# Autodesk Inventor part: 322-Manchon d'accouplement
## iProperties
Author: Philippe
Created: 2001-12
Part Number: 322-Manchon d'accouplement
Material: Par défaut
Document SubType Name: Modélisation
Designer: Philippe
Control State: 0
Master: False
Checked Out: False
PropertySet Name: Design Tracking Control
Shininess: 50.0
Angle Display Precision: 2
Document Length Units: 11269
Document Angle Units: 11283
Document Time Units: 11279
Document Mass Units: 11290
Document Length Units Precision: 3
Document Angle Units Precision: 2
Compacted: False
PropertySet Name: _Private Model Information
Density: 0.0
Volumn: 0.0
Area: 0.0
PropertySet Name: Model Information
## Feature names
1. Révolution1 [Revolution]
2. Perçage1 [Hole]
3. Perçage2 [Hole]
